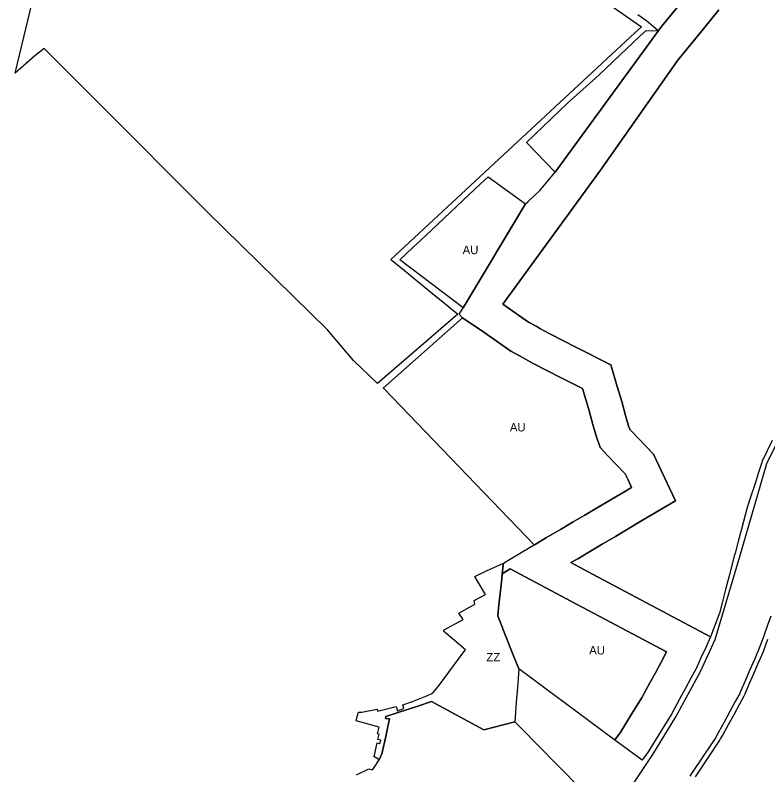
# Model space of a CAD drawing. Extents: x -537068 to -534056, y -1176840 to -1172401.
# Drawn here: x -535516.5 to -535072.7, y -1175536.1 to -1175088 of the extents above; entities that cross this region are included whole.
import ezdxf

# ---------------------------------------------------------------- set-up
doc = ezdxf.new("R2010")
doc.units = 0
for name, color, linetype in [('90550013', 7, 'Continuous'), ('90640013', 7, 'Continuous'), ('90670013', 7, 'Continuous'), ('90710023', 7, 'Continuous'), ('90750013', 7, 'Continuous')]:
    doc.layers.add(name, color=color, linetype=linetype)

msp = doc.modelspace()

# ---------------------------------------------------------------- linework, layer by layer
at = {"layer": '90550013'}
msp.add_lwpolyline([(-535115.3, -1175537.22), (-535107.39, -1175525.43), (-535100.87, -1175515.7), (-535100.46, -1175514.95), (-535099.24, -1175512.71), (-535095.81, -1175506.41), (-535092.59, -1175500.51), (-535089.2, -1175494.3), (-535086.6, -1175489.54), (-535086.08, -1175488.33), (-535083.23, -1175481.75), (-535080.73, -1175475.98), (-535077.92, -1175469.5), (-535075.27, -1175463.37), (-535075.07, -1175462.83), (-535072.61, -1175456.03)], dxfattribs=at)
at = {"layer": '90640013'}
for points in [[(-535157.02, -1175548.97), (-535140.56, -1175524.19), (-535126.93, -1175501.89), (-535112.4, -1175475.25), (-535103.65, -1175456.2), (-535089.06, -1175407.38), (-535073.18, -1175352.43), (-535046.44, -1175297.98)], [(-535070.86, -1175442.43), (-535072.82, -1175447.85), (-535075.28, -1175454.63), (-535077.75, -1175461.45), (-535078.08, -1175462.35), (-535080.57, -1175468.1), (-535083.38, -1175474.6), (-535085.87, -1175480.35), (-535088.72, -1175486.92), (-535089.24, -1175488.11), (-535091.84, -1175492.9), (-535095.22, -1175499.11), (-535098.45, -1175505.03), (-535101.89, -1175511.35), (-535103.09, -1175513.57), (-535103.35, -1175514.04), (-535110.04, -1175524.01), (-535117.97, -1175535.84), (-535118.65, -1175536.85)]]:
    msp.add_lwpolyline(points, dxfattribs=at)
at = {"layer": '90670013'}
msp.add_lwpolyline([(-535229.26, -1175417.53), (-535229.58, -1175420.48), (-535230.53, -1175429.24), (-535231.44, -1175437.65), (-535231.73, -1175440.38), (-535231.93, -1175442.23), (-535227.46, -1175453.5), (-535222.54, -1175465.89), (-535219.48, -1175473.62), (-535220.14, -1175482.22), (-535221, -1175493.43), (-535221.87, -1175504.8), (-535240.06, -1175509.59), (-535271.01, -1175492.91), (-535279.04, -1175495.56), (-535290.75, -1175499.43), (-535297.91, -1175501.8), (-535298.04, -1175502.82), (-535295.67, -1175503.15), (-535297.09, -1175509.58), (-535297.94, -1175513.44), (-535300.02, -1175522.9), (-535300.35, -1175523.7), (-535301.8, -1175527.25), (-535302.63, -1175526.72), (-535304.91, -1175525.27), (-535304.71, -1175524.56), (-535303.1, -1175517.24), (-535301.42, -1175517.73), (-535300.96, -1175515.76), (-535302.67, -1175515.33), (-535301.92, -1175512.2), (-535302.86, -1175511.87), (-535301.93, -1175508.06), (-535315.48, -1175504.21), (-535315.26, -1175503.48), (-535314.74, -1175501.72), (-535314, -1175499.23), (-535312.01, -1175499.24), (-535303.09, -1175497.48), (-535302.91, -1175498.53), (-535291.87, -1175495.77), (-535291.13, -1175498.29), (-535287.31, -1175497.07), (-535287.81, -1175494.78), (-535282.17, -1175492.92), (-535273.38, -1175489.28), (-535270.71, -1175488.17), (-535269.83, -1175487.39), (-535266.26, -1175483.04), (-535251.27, -1175462.7), (-535251.01, -1175462.37), (-535263.94, -1175451.33), (-535263.71, -1175451.19), (-535263.98, -1175450.86), (-535252.27, -1175444.54), (-535254.87, -1175440.66), (-535245.46, -1175435.51), (-535245.84, -1175433.37), (-535239.24, -1175429.81), (-535244.14, -1175421.54), (-535245.45, -1175419.18), (-535243.87, -1175418.43), (-535238.48, -1175415.87), (-535228.57, -1175411.16), (-535228.7, -1175412.38)], close=True, dxfattribs=at)
at = {"layer": '90710023'}
msp.add_lwpolyline([(-535101.57, -1175084.82), (-535110.63, -1175096), (-535125.65, -1175114.54), (-535171.35, -1175179.43), (-535228.84, -1175258.49), (-535213.77, -1175269.12), (-535208.97, -1175271.6), (-535207.07, -1175272.72), (-535201.25, -1175275.98), (-535185.43, -1175284.03), (-535165.16, -1175294.32), (-535161.42, -1175307.02), (-535158.83, -1175315.85), (-535156.55, -1175324.14), (-535155.03, -1175329.66), (-535154.08, -1175332.44), (-535152.92, -1175333.64), (-535140.01, -1175347.02), (-535136.92, -1175353.62), (-535127.13, -1175374.47), (-535147.45, -1175386.52), (-535162.53, -1175395.44), (-535170.42, -1175400.1), (-535177.19, -1175404.11), (-535184.79, -1175408.61), (-535188.76, -1175410.94), (-535176.04, -1175417.7), (-535106.48, -1175454.72), (-535106.52, -1175454.81), (-535109.28, -1175460.96), (-535111.87, -1175466.75), (-535114.68, -1175473.01), (-535115.02, -1175473.77), (-535117.96, -1175479.18), (-535121.39, -1175485.47), (-535124.69, -1175491.52), (-535128.36, -1175498.25), (-535129.49, -1175500.32), (-535135.96, -1175510.86), (-535143.17, -1175522.62), (-535146.84, -1175527.49), (-535162.85, -1175515.62), (-535162.81, -1175515.45), (-535159.72, -1175511.35), (-535153.01, -1175500.4), (-535146.8, -1175490.29), (-535145.92, -1175488.67), (-535142.25, -1175481.94), (-535138.95, -1175475.89), (-535135.57, -1175469.7), (-535132.34, -1175463.62), (-535132.33, -1175463.62), (-535185.43, -1175435.36), (-535224.55, -1175414.58), (-535229.26, -1175417.53), (-535228.7, -1175412.38), (-535228.57, -1175411.16), (-535223.96, -1175408.45), (-535217.14, -1175404.43), (-535210.45, -1175400.5), (-535209.89, -1175400.17), (-535203.11, -1175396.18), (-535194.95, -1175391.38), (-535187.38, -1175386.9), (-535180.61, -1175382.89), (-535172.71, -1175378.22), (-535157.64, -1175369.31), (-535152.95, -1175366.53), (-535155.02, -1175362.12), (-535156.71, -1175358.52), (-535167.31, -1175347.53), (-535171.58, -1175343.11), (-535174.15, -1175335.54), (-535175.83, -1175329.46), (-535178.07, -1175321.32), (-535180.61, -1175312.66), (-535181.91, -1175308.25), (-535194.49, -1175301.86), (-535210.68, -1175293.62), (-535212.81, -1175292.54), (-535217.02, -1175290.07), (-535218.64, -1175289.12), (-535224.18, -1175286.25), (-535240.2, -1175274.95), (-535252.65, -1175266.55), (-535254.7, -1175264.4), (-535252.39, -1175260.55), (-535215.63, -1175199.34), (-535213.98, -1175197.78), (-535206.98, -1175191.18), (-535198.15, -1175180.48), (-535135.27, -1175094.64), (-535126.17, -1175083.41)], dxfattribs=at)
at = {"layer": '90750013'}
for points in [[(-535175.51, -1175074.96), (-535147.24, -1175094.77), (-535151.14, -1175098.4), (-535294.94, -1175232.04), (-535290.22, -1175235.89), (-535271.33, -1175251.31), (-535261.08, -1175259.67), (-535255.37, -1175264.33), (-535302.84, -1175305.19), (-535316.92, -1175291.73), (-535332.39, -1175273.53), (-535403.27, -1175203.94), (-535467.22, -1175139.77), (-535470.66, -1175136.32), (-535499.35, -1175107.52), (-535504.94, -1175111.95), (-535516.52, -1175122.16), (-535500.18, -1175054.15)], [(-535126.17, -1175083.41), (-535135.27, -1175094.64), (-535198.15, -1175180.48), (-535215.05, -1175162.99), (-535190.77, -1175139.87), (-535174.24, -1175125.08), (-535171.9, -1175122.87), (-535148.04, -1175100.34), (-535144.39, -1175096.9), (-535137.28, -1175097.12), (-535140.17, -1175094.69), (-535144.09, -1175091.41), (-535149.3, -1175087.74)], [(-535070.02, -1175338.97), (-535075.96, -1175351.06), (-535076.19, -1175351.77), (-535078.28, -1175358.28), (-535080.36, -1175364.76), (-535082.78, -1175372.28), (-535084.77, -1175378.46), (-535088.14, -1175391.1), (-535090.09, -1175398.4), (-535091.94, -1175405.34), (-535092.23, -1175406.41), (-535095.64, -1175419.43), (-535097.55, -1175426.71), (-535099.43, -1175433.9), (-535101.22, -1175440.74), (-535101.51, -1175441.83), (-535103.71, -1175447.53), (-535106.48, -1175454.72), (-535176.04, -1175417.7), (-535188.76, -1175410.94), (-535184.79, -1175408.61), (-535177.19, -1175404.11), (-535170.42, -1175400.1), (-535162.53, -1175395.44), (-535147.45, -1175386.52), (-535127.13, -1175374.47), (-535136.92, -1175353.62), (-535140.01, -1175347.02), (-535152.92, -1175333.64), (-535154.08, -1175332.44), (-535155.03, -1175329.66), (-535156.55, -1175324.14), (-535158.83, -1175315.85), (-535161.42, -1175307.02), (-535165.16, -1175294.32), (-535185.43, -1175284.03), (-535201.25, -1175275.98), (-535207.07, -1175272.72), (-535208.97, -1175271.6), (-535213.77, -1175269.12), (-535228.84, -1175258.49), (-535171.35, -1175179.43), (-535125.65, -1175114.54), (-535110.63, -1175096), (-535101.57, -1175084.82)], [(-535315.16, -1175536.2), (-535307.97, -1175532.5), (-535305.79, -1175533.14), (-535305.22, -1175532.3), (-535301.8, -1175527.25), (-535300.35, -1175523.7), (-535300.02, -1175522.9), (-535297.94, -1175513.44), (-535297.09, -1175509.58), (-535295.67, -1175503.15), (-535298.04, -1175502.82), (-535297.91, -1175501.8), (-535290.75, -1175499.43), (-535279.04, -1175495.56), (-535271.01, -1175492.91), (-535240.06, -1175509.59), (-535221.87, -1175504.8), (-535218.59, -1175508.14), (-535196.65, -1175530.43), (-535182.22, -1175545.09)]]:
    msp.add_lwpolyline(points, dxfattribs=at)
for points in [[(-535215.63, -1175199.34), (-535252.39, -1175260.55), (-535289.65, -1175232.2), (-535281.94, -1175224.98), (-535274.41, -1175217.92), (-535263.71, -1175207.89), (-535259.81, -1175204.23), (-535256.36, -1175200.99), (-535252.09, -1175196.99), (-535242.22, -1175187.74), (-535237.5, -1175183.32)], [(-535210.45, -1175400.5), (-535299.15, -1175308.28), (-535299.55, -1175307.94), (-535252.65, -1175266.55), (-535240.2, -1175274.95), (-535224.18, -1175286.25), (-535218.64, -1175289.12), (-535217.02, -1175290.07), (-535212.81, -1175292.54), (-535210.68, -1175293.62), (-535194.49, -1175301.86), (-535181.91, -1175308.25), (-535180.61, -1175312.66), (-535178.07, -1175321.32), (-535175.83, -1175329.46), (-535174.15, -1175335.54), (-535171.58, -1175343.11), (-535167.31, -1175347.53), (-535156.71, -1175358.52), (-535155.02, -1175362.12), (-535152.95, -1175366.53), (-535157.64, -1175369.31), (-535172.71, -1175378.22), (-535180.61, -1175382.89), (-535187.38, -1175386.9), (-535194.95, -1175391.38), (-535203.11, -1175396.18), (-535209.89, -1175400.17)], [(-535229.26, -1175417.53), (-535224.55, -1175414.58), (-535185.43, -1175435.36), (-535132.33, -1175463.62), (-535132.34, -1175463.62), (-535135.57, -1175469.7), (-535138.95, -1175475.89), (-535142.25, -1175481.94), (-535145.92, -1175488.67), (-535146.8, -1175490.29), (-535153.01, -1175500.4), (-535159.72, -1175511.35), (-535162.81, -1175515.45), (-535162.85, -1175515.62), (-535178.2, -1175504.23), (-535219.48, -1175473.62), (-535222.54, -1175465.89), (-535227.46, -1175453.5), (-535231.93, -1175442.23), (-535231.73, -1175440.38), (-535231.44, -1175437.65), (-535230.53, -1175429.24), (-535229.58, -1175420.48)]]:
    msp.add_lwpolyline(points, close=True, dxfattribs=at)

# ---------------------------------------------------------------- texts
at = {"layer": '90670013'}
msp.add_text('ZZ', height=5, rotation=360, dxfattribs=at).set_placement((-535238.65, -1175469.21))
at = {"layer": '90750013'}
for rotation, p in [(360, (-535252.64, -1175228.93)), (0, (-535224.79, -1175333.53)), (0, (-535177.99, -1175465.1))]:
    msp.add_text('AU', height=5, rotation=rotation, dxfattribs=at).set_placement(p)

doc.saveas('drawing.dxf')
